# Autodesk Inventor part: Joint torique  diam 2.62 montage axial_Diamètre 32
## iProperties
Shininess: 64.0
Length Units: 11269
Angle Units: 11279
Time Units: 11290
Mass Units: 11283
Length Display Precision: 3
Angle Display Precision: 2
Compacted: True
Part Number: Joint torique  diam 2.62 montage axial_Diamètre 32
Document SubType Name: Modeling
Created: 2006-01
Material: Par défaut
Designer: riri
Density: 0.0
Volumn: 0.0
Area: 0.0
PropertySet Name: Model Information
Control State: 0
Master: False
Checked Out: False
Author: riri
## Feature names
1. Base1
